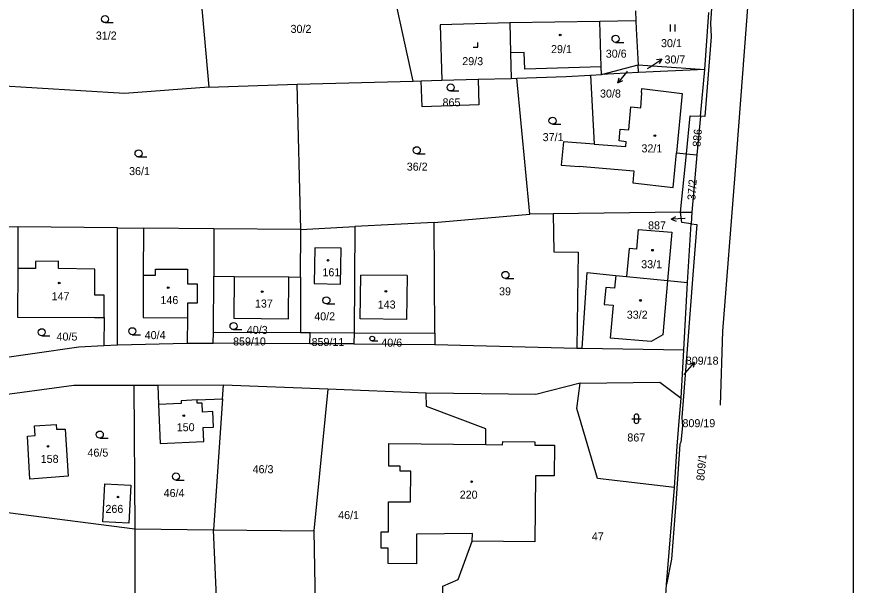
# Model space of a CAD drawing. Extents: x -553916 to -552953, y -1067470 to -1066637.
# Drawn here: x -553477.6 to -553300, y -1067275.4 to -1067154.7 of the extents above; entities that cross this region are included whole.
import ezdxf

# ---------------------------------------------------------------- set-up
doc = ezdxf.new("R2010")
doc.units = 0
for name, color, linetype in [('Hranice parcel', 7, 'Continuous'), ('Parcelní čísla', 7, 'Continuous'), ('Pop  PČ popisy', 7, 'Continuous'), ('Vnitřní kresba', 7, 'Continuous'), ('Vrstva 1', 7, 'Continuous'), ('Značky budov', 7, 'Continuous'), ('Značky kultur', 7, 'Continuous')]:
    doc.layers.add(name, color=color, linetype=linetype)

msp = doc.modelspace()

# ---------------------------------------------------------------- linework, layer by layer
at = {"layer": 'Hranice parcel'}
for p, q in [((-553393.46, -1067168.37), (-553399.58, -1067140.36)), ((-553439.36, -1067141.68), (-553436.84, -1067169.66)), ((-553346.27, -1067153.44), (-553346.16, -1067155.58)), ((-553331.55, -1067165.94), (-553330.68, -1067153.79)), ((-553353.83, -1067155.7), (-553372.95, -1067155.98)), ((-553346.16, -1067155.58), (-553353.83, -1067155.7)), ((-553353.49, -1067166.99), (-553345.68, -1067164.9)), ((-553345.68, -1067164.9), (-553331.55, -1067165.94)), ((-553345.58, -1067166.56), (-553345.68, -1067164.9)), ((-553355.76, -1067167.11), (-553353.49, -1067166.99)), ((-553345.58, -1067166.56), (-553353.49, -1067166.99)), ((-553331.55, -1067165.94), (-553345.58, -1067166.56)), ((-553332.44, -1067175.8), (-553331.55, -1067165.94)), ((-553436.84, -1067169.66), (-553418.08, -1067169.04)), ((-553418.08, -1067169.04), (-553393.46, -1067168.37)), ((-553417.29, -1067199.86), (-553418.08, -1067169.04)), ((-553393.46, -1067168.37), (-553391.73, -1067168.32)), ((-553391.73, -1067168.32), (-553387.35, -1067168.2)), ((-553387.35, -1067168.2), (-553379.66, -1067167.99)), ((-553379.66, -1067167.99), (-553372.62, -1067167.8)), ((-553372.62, -1067167.8), (-553371.42, -1067167.77)), ((-553368.66, -1067196.58), (-553371.42, -1067167.77)), ((-553332.44, -1067175.8), (-553333.19, -1067184)), ((-553331.52, -1067175.88), (-553332.44, -1067175.8)), ((-553336.65, -1067196.18), (-553335.4, -1067183.78)), ((-553335.4, -1067183.78), (-553333.19, -1067184)), ((-553333.19, -1067184), (-553334.29, -1067196.15)), ((-553388.98, -1067198.37), (-553368.66, -1067196.58)), ((-553363.69, -1067196.52), (-553368.66, -1067196.58)), ((-553336.65, -1067196.18), (-553363.69, -1067196.52)), ((-553336.65, -1067196.18), (-553334.29, -1067196.15)), ((-553334.29, -1067196.15), (-553334.44, -1067198.66)), ((-553484.83, -1067199.23), (-553477.39, -1067199.3)), ((-553456.25, -1067199.5), (-553477.39, -1067199.3)), ((-553417.29, -1067199.86), (-553405.8, -1067199.26)), ((-553405.8, -1067199.26), (-553406.01, -1067221.76)), ((-553388.98, -1067198.37), (-553405.8, -1067199.26)), ((-553388.88, -1067221.84), (-553388.98, -1067198.37)), ((-553335.21, -1067211.14), (-553334.44, -1067198.66)), ((-553334.44, -1067198.66), (-553333.24, -1067198.82)), ((-553456.25, -1067224.37), (-553456.25, -1067199.5)), ((-553456.25, -1067199.5), (-553450.73, -1067199.55)), ((-553450.73, -1067199.55), (-553450.76, -1067209.56)), ((-553435.75, -1067199.69), (-553450.73, -1067199.55)), ((-553435.75, -1067199.69), (-553435.8, -1067209.76)), ((-553417.29, -1067199.86), (-553435.75, -1067199.69)), ((-553417.34, -1067209.97), (-553417.29, -1067199.86)), ((-553435.87, -1067221.63), (-553435.8, -1067209.76)), ((-553435.8, -1067209.76), (-553431.44, -1067209.81)), ((-553419.84, -1067209.94), (-553417.34, -1067209.97)), ((-553417.34, -1067209.97), (-553417.4, -1067221.71)), ((-553335.99, -1067225.37), (-553335.21, -1067211.14)), ((-553461.09, -1067218.52), (-553459.09, -1067218.53)), ((-553459.09, -1067218.53), (-553459.11, -1067224.45)), ((-553441.39, -1067218.6), (-553441.41, -1067223.95)), ((-553435.89, -1067223.95), (-553435.87, -1067221.63)), ((-553435.87, -1067221.63), (-553417.4, -1067221.71)), ((-553417.4, -1067221.71), (-553415.35, -1067221.72)), ((-553415.37, -1067224.09), (-553415.35, -1067221.72)), ((-553415.35, -1067221.72), (-553406.01, -1067221.76)), ((-553406.01, -1067221.76), (-553406.03, -1067224.15)), ((-553406.01, -1067221.76), (-553388.88, -1067221.84)), ((-553388.88, -1067221.84), (-553388.87, -1067224.27)), ((-553456.25, -1067224.37), (-553441.41, -1067223.95)), ((-553441.41, -1067223.95), (-553435.89, -1067223.95)), ((-553415.37, -1067224.09), (-553435.89, -1067223.95)), ((-553406.03, -1067224.15), (-553415.37, -1067224.09)), ((-553406.03, -1067224.15), (-553388.87, -1067224.27)), ((-553388.87, -1067224.27), (-553358.72, -1067225.01)), ((-553459.11, -1067224.45), (-553456.25, -1067224.37)), ((-553358.72, -1067225.01), (-553357.54, -1067225.03)), ((-553357.54, -1067225.03), (-553335.99, -1067225.37)), ((-553336.55, -1067235.64), (-553335.99, -1067225.37)), ((-553447.69, -1067232.94), (-553452.74, -1067232.95)), ((-553452.74, -1067232.95), (-553452.56, -1067263.4)), ((-553433.75, -1067232.91), (-553447.69, -1067232.94)), ((-553433.9, -1067235.81), (-553433.75, -1067232.91)), ((-553411.56, -1067233.76), (-553433.75, -1067232.91)), ((-553411.56, -1067233.76), (-553414.54, -1067263.83)), ((-553390.7, -1067234.56), (-553411.56, -1067233.76)), ((-553433.9, -1067235.81), (-553435.83, -1067263.59)), ((-553398.6, -1067245.25), (-553377.99, -1067245.49)), ((-553377.99, -1067245.49), (-553374.45, -1067245.53)), ((-553339.64, -1067275.16), (-553337.96, -1067254.64)), ((-553482.12, -1067259.57), (-553452.56, -1067263.4)), ((-553452.56, -1067263.4), (-553435.83, -1067263.59)), ((-553452.56, -1067263.4), (-553452.48, -1067309.26)), ((-553435.83, -1067263.59), (-553414.54, -1067263.83)), ((-553434.32, -1067299.29), (-553435.83, -1067263.59)), ((-553414.54, -1067263.83), (-553414.1, -1067291.02)), ((-553339.78, -1067277.49), (-553339.64, -1067275.16))]:
    msp.add_line(p, q, dxfattribs=at)
for points in [[(-553328.17, -1067237.16), (-553327.73, -1067221.42), (-553325.1, -1067188.21), (-553321.08, -1067135.94), (-553318.8, -1067106.18), (-553318.16, -1067094.26)], [(-553326.43, -1067110.03), (-553327.44, -1067125.38), (-553329.15, -1067146.93), (-553329.8, -1067148.66), (-553330.31, -1067156.1), (-553330.14, -1067159), (-553331.52, -1067175.88)], [(-553372.95, -1067155.98), (-553387.69, -1067156.41), (-553387.35, -1067168.2)], [(-553372.95, -1067155.98), (-553372.77, -1067162.39), (-553372.62, -1067167.8)], [(-553353.49, -1067166.99), (-553353.54, -1067165.32), (-553353.83, -1067155.7)], [(-553346.16, -1067155.58), (-553346.08, -1067157.3), (-553345.68, -1067164.9)], [(-553371.42, -1067167.77), (-553360.93, -1067167.39), (-553355.76, -1067167.11)], [(-553355.76, -1067167.11), (-553354.99, -1067181.75), (-553361.56, -1067181.24)], [(-553379.66, -1067167.99), (-553379.51, -1067173.39), (-553391.56, -1067173.82), (-553391.73, -1067168.32)], [(-553436.84, -1067169.66), (-553454.76, -1067170.99), (-553482.63, -1067169.28)], [(-553335.4, -1067183.78), (-553334.63, -1067175.73), (-553332.44, -1067175.8)], [(-553361.56, -1067181.24), (-553362.01, -1067186.18), (-553358.19, -1067186.49), (-553358.18, -1067186.39), (-553346.59, -1067187.42), (-553346.84, -1067189.99)], [(-553346.84, -1067189.99), (-553338.23, -1067190.96), (-553337.52, -1067183.58), (-553335.4, -1067183.78)], [(-553363.69, -1067196.52), (-553363.6, -1067204.58), (-553358.44, -1067204.66), (-553358.72, -1067225.01)], [(-553334.44, -1067198.66), (-553336.38, -1067198.39), (-553336.65, -1067196.18)], [(-553477.39, -1067199.3), (-553477.42, -1067208.16), (-553477.45, -1067218.47), (-553461.09, -1067218.52)], [(-553333.24, -1067198.82), (-553334.06, -1067209.45), (-553335.19, -1067224.37), (-553336.43, -1067239.75), (-553336.33, -1067240.75), (-553336.29, -1067241.53), (-553336.59, -1067245.01), (-553336.81, -1067245.42), (-553337.63, -1067256.92), (-553338.62, -1067269.85), (-553339.64, -1067275.16)], [(-553408.86, -1067211.44), (-553408.74, -1067203.85), (-553414.34, -1067203.76), (-553414.46, -1067211.35), (-553408.86, -1067211.44)], [(-553450.76, -1067209.56), (-553450.79, -1067218.56), (-553441.39, -1067218.6)], [(-553431.44, -1067209.81), (-553431.54, -1067218.71), (-553419.94, -1067218.84), (-553419.84, -1067209.94)], [(-553357.54, -1067225.03), (-553356.49, -1067209), (-553350.44, -1067209.61), (-553348.15, -1067209.84), (-553339.41, -1067210.72), (-553335.21, -1067211.14)], [(-553494.01, -1067229.02), (-553464.41, -1067224.79), (-553459.11, -1067224.45)], [(-553452.74, -1067232.95), (-553465.5, -1067232.97), (-553483.33, -1067235.39)], [(-553447.69, -1067232.94), (-553447.5, -1067237.03), (-553447.14, -1067245.25), (-553437.9, -1067244.85), (-553438.03, -1067241.9), (-553435.84, -1067241.8), (-553435.98, -1067238.49), (-553438.18, -1067238.59), (-553438.26, -1067236.69), (-553439.31, -1067236.74), (-553439.34, -1067236.04), (-553433.9, -1067235.81)], [(-553357.99, -1067232.47), (-553367.43, -1067234.89), (-553390.7, -1067234.56)], [(-553337.96, -1067254.64), (-553354.3, -1067252.71), (-553358.68, -1067237.85), (-553357.99, -1067232.47)], [(-553357.99, -1067232.47), (-553341.1, -1067232.29), (-553336.55, -1067235.64)], [(-553377.99, -1067245.49), (-553378.02, -1067242.17), (-553390.61, -1067237.39), (-553390.7, -1067234.56)], [(-553337.96, -1067254.64), (-553337.4, -1067245.83), (-553336.98, -1067240.51), (-553336.55, -1067235.64)], [(-553467.35, -1067242.2), (-553466.7, -1067252.22), (-553474.81, -1067252.81), (-553475.34, -1067243.72), (-553473.73, -1067243.61), (-553473.86, -1067241.5), (-553469.23, -1067241.21), (-553469.17, -1067242.22), (-553467.35, -1067242.2)], [(-553380.89, -1067266), (-553380.88, -1067264.4), (-553392.71, -1067264.49), (-553392.73, -1067270.79), (-553398.74, -1067270.76), (-553398.73, -1067267.45), (-553400.25, -1067267.45), (-553400.24, -1067264.02), (-553398.7, -1067264.03), (-553398.67, -1067257.63), (-553394.03, -1067257.66), (-553393.95, -1067251.16), (-553396.2, -1067251.13), (-553396.2, -1067250.08), (-553398.63, -1067250.06), (-553398.6, -1067245.25)], [(-553374.45, -1067245.53), (-553374.44, -1067244.83), (-553367.61, -1067244.92), (-553367.62, -1067245.61), (-553363.43, -1067245.65), (-553363.51, -1067252.16), (-553367.46, -1067252.12), (-553367.63, -1067266.17), (-553380.89, -1067266)], [(-553459.36, -1067261.9), (-553458.95, -1067253.83), (-553453.4, -1067254.12), (-553453.81, -1067262.19), (-553459.36, -1067261.9)], [(-553387.06, -1067279.96), (-553387.14, -1067275.52), (-553383.92, -1067274.15), (-553380.89, -1067266)]]:
    msp.add_lwpolyline(points, dxfattribs=at)
at = {"layer": 'Pop  PČ popisy'}
for p, q in [((-553343.18, -1067165.38), (-553340.66, -1067163.75)), ((-553340.66, -1067163.75), (-553341.78, -1067163.87)), ((-553340.66, -1067163.75), (-553341.23, -1067164.71)), ((-553343.66, -1067165.69), (-553343.18, -1067165.38)), ((-553348.11, -1067166.38), (-553349.96, -1067168.75)), ((-553348.01, -1067166.25), (-553348.11, -1067166.38)), ((-553349.96, -1067168.75), (-553349.74, -1067167.65)), ((-553349.96, -1067168.75), (-553348.95, -1067168.26)), ((-553338.67, -1067197.68), (-553337.69, -1067197.12)), ((-553335.67, -1067197.52), (-553338.67, -1067197.68)), ((-553338.67, -1067197.68), (-553337.64, -1067198.12)), ((-553335.69, -1067230.33), (-553333.72, -1067228.06)), ((-553333.72, -1067228.06), (-553334.76, -1067228.49)), ((-553333.72, -1067228.06), (-553334, -1067229.15)), ((-553335.97, -1067230.65), (-553335.69, -1067230.33))]:
    msp.add_line(p, q, dxfattribs=at)
at = {"layer": 'Vnitřní kresba'}
for p, q in [((-553369.87, -1067162.31), (-553372.77, -1067162.39)), ((-553369.77, -1067165.82), (-553369.87, -1067162.31)), ((-553353.54, -1067165.32), (-553369.77, -1067165.82)), ((-553345.14, -1067174.05), (-553344.86, -1067170.83)), ((-553345, -1067170.82), (-553344.9, -1067169.94)), ((-553344.86, -1067170.83), (-553345, -1067170.82)), ((-553344.9, -1067169.94), (-553336.33, -1067170.99)), ((-553336.33, -1067170.99), (-553337.52, -1067183.58)), ((-553347.67, -1067178.72), (-553347.23, -1067173.83)), ((-553347.23, -1067173.83), (-553345.14, -1067174.05)), ((-553349.71, -1067181.08), (-553349.48, -1067178.59)), ((-553349.48, -1067178.59), (-553347.67, -1067178.72)), ((-553348.21, -1067181.23), (-553349.71, -1067181.08)), ((-553348.3, -1067182.27), (-553348.21, -1067181.23)), ((-553354.99, -1067181.75), (-553348.3, -1067182.27)), ((-553345.64, -1067199.83), (-553346.06, -1067204.06)), ((-553345.64, -1067199.83), (-553338.51, -1067200.46)), ((-553338.51, -1067200.46), (-553339.41, -1067210.72)), ((-553347.55, -1067203.91), (-553348.15, -1067209.84)), ((-553346.06, -1067204.06), (-553347.55, -1067203.91)), ((-553473.65, -1067208.17), (-553477.42, -1067208.16)), ((-553468.76, -1067206.59), (-553473.65, -1067206.67)), ((-553473.65, -1067206.67), (-553473.65, -1067208.17)), ((-553468.77, -1067208.17), (-553468.76, -1067206.59)), ((-553461.05, -1067208.27), (-553468.77, -1067208.17)), ((-553461.07, -1067213.82), (-553461.05, -1067208.27)), ((-553448.16, -1067209.58), (-553448.15, -1067208.28)), ((-553448.15, -1067208.28), (-553441.35, -1067208.3)), ((-553441.35, -1067208.3), (-553441.36, -1067211.4)), ((-553450.76, -1067209.56), (-553448.16, -1067209.58)), ((-553431.44, -1067209.81), (-553419.84, -1067209.94)), ((-553404.67, -1067218.82), (-553404.55, -1067209.52)), ((-553394.75, -1067209.65), (-553404.55, -1067209.52)), ((-553394.75, -1067209.65), (-553394.87, -1067218.95)), ((-553350.44, -1067209.61), (-553350.68, -1067212.33)), ((-553441.36, -1067211.4), (-553439.31, -1067211.41)), ((-553439.31, -1067211.41), (-553439.33, -1067215.51)), ((-553339.41, -1067210.72), (-553340.42, -1067222.22)), ((-553352.57, -1067212.16), (-553352.89, -1067215.75)), ((-553350.68, -1067212.33), (-553352.57, -1067212.16)), ((-553459.07, -1067213.83), (-553461.07, -1067213.82)), ((-553459.09, -1067218.53), (-553459.07, -1067213.83)), ((-553441.38, -1067215.5), (-553441.39, -1067218.6)), ((-553439.33, -1067215.51), (-553441.38, -1067215.5)), ((-553352.89, -1067215.75), (-553351, -1067215.91)), ((-553351, -1067215.91), (-553351.62, -1067222.89)), ((-553394.87, -1067218.95), (-553404.67, -1067218.82)), ((-553340.42, -1067222.22), (-553342.92, -1067223.66)), ((-553342.92, -1067223.66), (-553351.62, -1067222.89)), ((-553439.34, -1067236.04), (-553442.74, -1067236.19)), ((-553442.74, -1067236.19), (-553442.71, -1067236.81)), ((-553442.71, -1067236.81), (-553447.5, -1067237.03))]:
    msp.add_line(p, q, dxfattribs=at)
at = {"layer": 'Vrstva 1'}
msp.add_lwpolyline([(-553800, -1067410.27), (-553800, -1067100), (-553300, -1067100), (-553300, -1067410.27)], dxfattribs=at)
at = {"layer": 'Značky budov'}
for centre in [(-553362.22, -1067158.58), (-553342.13, -1067179.95), (-553342.63, -1067204.26), (-553411.53, -1067206.4), (-553468.6, -1067211.23), (-553445.46, -1067212.22), (-553425.5, -1067213.05), (-553399.25, -1067213), (-553345.18, -1067214.92), (-553442.16, -1067239.37), (-553471, -1067245.89), (-553381.04, -1067253.39), (-553456.11, -1067256.63)]:
    msp.add_circle(centre, 0.175, dxfattribs=at)
at = {"layer": 'Značky kultur'}
for p, q in [((-553458.87, -1067155.97), (-553457.12, -1067155.97)), ((-553338.84, -1067157.86), (-553338.84, -1067156.36)), ((-553337.84, -1067157.86), (-553337.84, -1067156.36)), ((-553379.74, -1067161.2), (-553379.74, -1067160.2)), ((-553350.47, -1067160.15), (-553348.72, -1067160.15)), ((-553380.74, -1067161.2), (-553379.74, -1067161.2)), ((-553385.49, -1067170.47), (-553383.74, -1067170.47)), ((-553363.86, -1067177.53), (-553362.11, -1067177.53)), ((-553451.76, -1067184.47), (-553450.01, -1067184.47)), ((-553392.68, -1067183.79), (-553390.93, -1067183.79)), ((-553373.85, -1067210.24), (-553372.1, -1067210.24)), ((-553411.86, -1067215.65), (-553410.11, -1067215.65)), ((-553472.32, -1067222.41), (-553470.57, -1067222.41)), ((-553453.08, -1067222.2), (-553451.33, -1067222.2)), ((-553431.59, -1067221.11), (-553429.84, -1067221.11)), ((-553402.15, -1067223.5), (-553400.97, -1067223.5)), ((-553347.05, -1067240.02), (-553345.05, -1067240.02)), ((-553346.55, -1067239.52), (-553346.55, -1067240.52)), ((-553345.55, -1067240.52), (-553345.55, -1067239.52)), ((-553459.99, -1067244.13), (-553458.24, -1067244.13)), ((-553443.82, -1067253.02), (-553442.07, -1067253.02))]:
    msp.add_line(p, q, dxfattribs=at)
for centre, radius in [((-553458.87, -1067155.22), 0.75), ((-553350.47, -1067159.4), 0.75), ((-553385.49, -1067169.72), 0.75), ((-553363.86, -1067176.78), 0.75), ((-553451.76, -1067183.72), 0.75), ((-553392.68, -1067183.04), 0.75), ((-553373.85, -1067209.49), 0.75), ((-553411.86, -1067214.9), 0.75), ((-553453.08, -1067221.45), 0.75), ((-553431.59, -1067220.36), 0.75), ((-553472.32, -1067221.66), 0.75), ((-553402.15, -1067223), 0.502), ((-553459.99, -1067243.38), 0.75), ((-553443.82, -1067252.27), 0.75)]:
    msp.add_circle(centre, radius, dxfattribs=at)
for centre, start, end in [((-553346.05, -1067239.52), 0, 180), ((-553346.05, -1067240.52), 180, 359.9879)]:
    msp.add_arc(centre, 0.5, start, end, dxfattribs=at)

# ---------------------------------------------------------------- texts
at = {"layer": 'Parcelní čísla'}
for s, p in [('30/2', (-553419.48, -1067158.14)), ('31/2', (-553460.83, -1067159.55)), ('30/1', (-553340.82, -1067161.17)), ('29/1', (-553364.17, -1067162.43)), ('30/6', (-553352.55, -1067163.4)), ('29/3', (-553383.02, -1067164.99)), ('30/7', (-553340.08, -1067164.63)), ('30/8', (-553353.77, -1067171.86)), ('865', (-553387.21, -1067173.73)), ('37/1', (-553365.95, -1067181.11)), ('32/1', (-553344.97, -1067183.5)), ('36/1', (-553453.77, -1067188.32)), ('36/2', (-553394.81, -1067187.37)), ('887', (-553343.57, -1067199.83)), ('33/1', (-553345.03, -1067208.08)), ('161', (-553412.71, -1067209.79)), ('147', (-553470.22, -1067214.87)), ('39', (-553375.21, -1067213.84)), ('146', (-553447.11, -1067215.69)), ('137', (-553427.04, -1067216.42)), ('143', (-553400.97, -1067216.63)), ('33/2', (-553348.09, -1067218.79)), ('40/2', (-553414.45, -1067219.14)), ('40/3', (-553428.77, -1067222.02)), ('40/5', (-553469.17, -1067223.44)), ('40/4', (-553450.45, -1067223.12)), ('859/10', (-553431.69, -1067224.47)), ('859/11', (-553415.02, -1067224.59)), ('40/6', (-553400.21, -1067224.72)), ('809/18', (-553335.56, -1067228.54)), ('809/19', (-553336.26, -1067241.81)), ('150', (-553443.65, -1067242.67)), ('867', (-553347.97, -1067244.85)), ('46/5', (-553462.6, -1067248.06)), ('158', (-553472.53, -1067249.39)), ('46/3', (-553427.54, -1067251.58)), ('46/4', (-553446.43, -1067256.63)), ('220', (-553383.56, -1067256.98)), ('266', (-553458.79, -1067260)), ('46/1', (-553409.37, -1067261.31)), ('47', (-553355.51, -1067265.82))]:
    msp.add_text(s, height=1.7, dxfattribs=at).set_placement(p)
for s, rotation, p in [('886', 85, (-553332.45, -1067182.39)), ('37/2', 86, (-553333.54, -1067193.69)), ('809/1', 85, (-553331.65, -1067253.23))]:
    msp.add_text(s, height=1.7, rotation=rotation, dxfattribs=at).set_placement(p)

doc.saveas('drawing.dxf')
